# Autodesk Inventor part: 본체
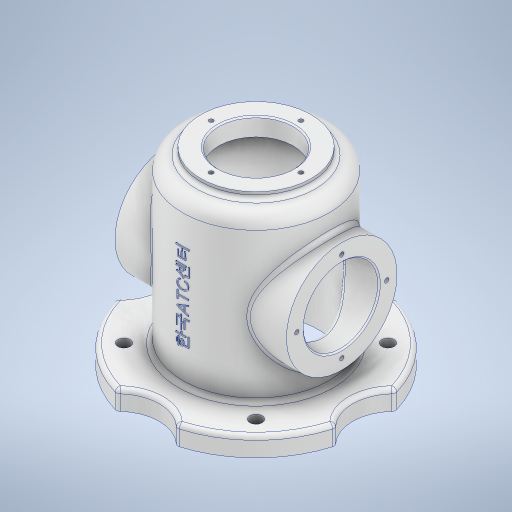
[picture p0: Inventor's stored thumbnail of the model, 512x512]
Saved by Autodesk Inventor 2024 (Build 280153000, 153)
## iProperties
Created: 2026-07
Part Number: 본체
Material: 알루미늄 6061
Document SubType Name: Modeling
Designer: com
Density: 2.7 g/cm^3
Appearance: 알루미늄 - 평지
Mass: 1503.84 g
Surface Area: 1242.71 cm^2
Volume: 556.978 cm^3
Author: com
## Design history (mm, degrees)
sketch "스케치1"
  geometry: L1 (0, 0)-(0, 137); L2 (40, 137)-(40, 132); L3 (40, 132)-(53, 132); L4 (53, 132)-(53, 0); L5 (53, 0)-(0, 0); L6 (40, 137)-(0, 137); L7 (0, 0)-(82, 0); L8 (82, 0)-(82, 14); L9 (82, 14)-(0, 14); L10 (0, 14)-(0, 0); 2 further points
  constraints: 20 end point, 5 perpendicular, 2 parallel, 1 horizontal, 1 vertical
  dimensions: "d0" = 137 distance of L1.start L1.end; "d1" = 5 distance of L2.start L2.end; "d2" = 80 diameter of L2 L1; "d3" = 106 diameter of L4 L1; "d4" = 164 diameter of L8 L1; "d5" = 14 distance between parallel lines of L5 L9
revolve "회전1" sketch "스케치1" stored, may be unused: angle "d6" = 90 deg
sketch "스케치2" dims "d22" = 0
  geometry: L1 (-62, 68)-(62, 68); L2 (0, 0)-(0, 143); L3 (82, 0)-(-82, 0) reference; L4 (-62, 68)-(-62, 108); L5 (-62, 108)-(62, 108); L6 (62, 108)-(62, 68); 2 further points
  constraints: 10 end point, 2 midpoint, 2 perpendicular, 2 vertical, 1 horizontal, 1 vertical alignment
  dimensions: "d7" = 68 distance between parallel lines of L3 L1; "d8" = 124 distance of L1.start L1.end; "d9" = 80 diameter of L5 L1
revolve "회전2" sketch "스케치2" stored, may be unused: angle "d10" = 90 deg
sketch "스케치3"
  geometry: L1 (0, 0)-(0, 171.391); L2 (82, 0)-(-82, 0) reference; L3 (-45, 0)-(-45, 121); L4 (-42, 124)-(0, 124); L5 (0, 124)-(-27, 124); L6 (-27, 124)-(-27, 137); L7 (-27, 137)-(0, 137); L8 (0, 137)-(0, 124); L9 (40, 137)-(-40, 137) reference; A1 r 3 centre (-42, 121) between (-42, 124) and (-45, 121); 4 further points
  constraints: 14 end point, 4 point on line, 2 midpoint, 2 parallel, 2 perpendicular, 2 point on circle, 2 tangent, 2 vertical, 1 centre point, 1 horizontal
  dimensions: "d11" = 54 diameter of point (-27, 130.5) L1; "d12" = 90 diameter of L3 L1; "d13" = 124 distance of L3.start point (-45, 124); "d14" = 3 radius of A1
revolve "회전3" sketch "스케치3" stored, may be unused: angle "d15" = 90 deg
sketch "스케치4"
  geometry: C1 r 40 at (0, 0) reference; C2 r 27 at (0, 0); 1 further point
  constraints: 1 centre point, 1 coincident
  dimensions: "d16" = 54 diameter of C2
extrude "돌출1" cut sketch "스케치4" extent not by distance; stored distance "d17" = 0; taper "d18" = 0 deg
fillet "모깎기1" dims "d19" = 3
sketch "스케치5"
  geometry: C1 r 30 at (-100, 0); 1 further point
  constraints: 1 centre point, 1 horizontal alignment
  dimensions: "d20" = 60 diameter of C1; "d21" = 100 distance of point (0, 0) C1.centre
extrude "돌출2" cut sketch "스케치5" extent not by distance; stored distance "d22" = 0; taper "d23" = 0 deg
sketch "스케치6"
  geometry: L1 (100, 0)-(100, 67.5); L2 (100, 0)-(52.27, 47.73); C1 r 4.5 at (52.27, 47.73); C2 r 4.5 at (52.27, -47.73); C3 r 4.5 at (147.73, -47.73); C4 r 4.5 at (147.73, 47.73); A1 r 67.5 centre (100, 0) between (52.27, 47.73) and (100, 67.5); 1 further point
  constraints: 5 centre point, 4 end point, 2 coincident, 2 point on circle, 1 vertical, 9 other
  dimensions: "d27" = 135 diameter of A1; "d28" = 45 deg angle of L1 L2; "d29" = 9 diameter of C1; "d32" = 360 deg dimension on point (100, 0) C1.centre (derived)
extrude "돌출3" cut sketch "스케치6" extent not by distance; stored distance "d34" = 0; taper "d35" = 0 deg
sketch "스케치7" dims "d36" = 65
  geometry: C1 r 27 at (0, 0) reference; 6 further points
  constraints: 2 vertical alignment, 1 coincident, 7 other
  dimensions: "d39" = 360 deg dimension on point (0, 0) point (0, 32.5) (derived)
hole "구멍1" sketch "스케치7" at (0, 32.5), (-32.5, 0), (0, -32.5), (32.5, 0) diameter "d41" = 3.242; stored, may be unused: countersink angle "d45" = 90 deg, drill point angle "d47" = 118 deg; dims "d42" = 8, "d43" = 10, "d44" = 5.7, "d46" = 10
sketch "스케치8" dims "d48" = 65
  geometry: C1 r 27 at (0, 0) reference; 6 further points
  constraints: 1 coincident, 1 vertical alignment, 7 other
  dimensions: "d51" = 360 deg dimension on point (0, 0) point (0, 32.5) (derived)
hole "구멍2" sketch "스케치8" at (0, 32.5), (-32.5, 0), (0, -32.5), (32.5, 0) diameter "d53" = 3.242; stored, may be unused: countersink angle "d57" = 90 deg, drill point angle "d59" = 118 deg; dims "d54" = 8, "d55" = 4, "d56" = 2, "d58" = 10
chamfer "모따기1" distance "d60" = 1; stored, may be unused: second distance "d61" = 2, angle "d62" = 45 deg
fillet "모깎기2" dims "d63" = 3
fillet "모깎기3" dims "d64" = 10
sketch "스케치9"
  geometry: L1 (45, 0)-(-45, 0) reference; 3 further points
  constraints: 1 midpoint, 1 vertical alignment, 1 other
  dimensions: "d65" = 70 distance from line of point (0, 70) L1
feature "엠보싱1" sketch "스케치9" dims "d0" = 137, "d1" = 5, "d2" = 80, "d3" = 106, "d4" = 164, "d5" = 14, "d66" = 0.5, "d67" = 0
fillet "모깎기4" dims "d68" = 3
node "솔리드1"
pattern_circular "원형 패턴1" dims angle "d25" = 360 deg
mirror "미러1"
feature "A9D066F2-1C7D-4E18-AEED-F7BC21143FA4" dims "d41" = 3.242, "d42" = 8, "d43" = 10, "d44" = 5.7, "d45" = 90 deg, "d46" = 10, "d47" = 118 deg
